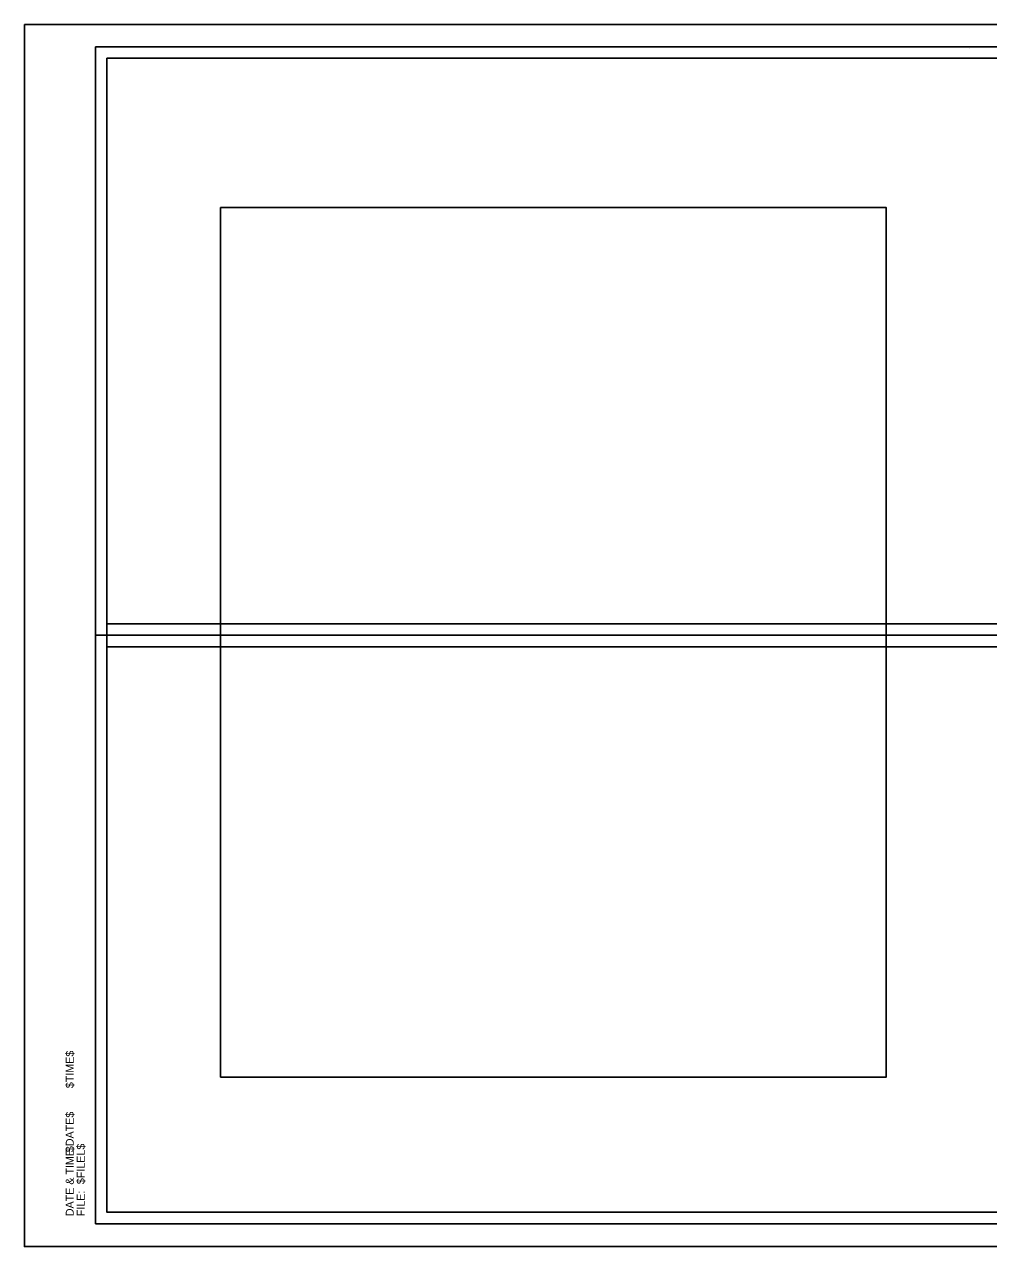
# Model space of a CAD drawing. Extents: x 1369290 to 1369980, y 379348 to 379562.
# Drawn here: x 1369646.8 to 1369815.1, y 379348.4 to 379561.7 of the extents above; entities that cross this region are included whole.
import ezdxf

# ---------------------------------------------------------------- set-up
doc = ezdxf.new("R2010")
doc.units = 0
for name, color, linetype in [('Default', 7, 'Continuous'), ('R_Border', 7, 'Continuous'), ('R_Border Notes', 7, 'Continuous'), ('R_Border Plan-Plan', 7, 'Continuous'), ('R_No Plot', 7, 'Continuous')]:
    doc.layers.add(name, color=color, linetype=linetype)

msp = doc.modelspace()

# ---------------------------------------------------------------- linework, layer by layer
at = {"layer": 'Default'}
msp.add_lwpolyline([(1369681.07, 379377.98), (1369797.24, 379377.98), (1369797.24, 379529.77), (1369681.07, 379529.77)], close=True, dxfattribs=at)
at = {"layer": 'R_Border'}
for p, q in [((1369659.23, 379557.83), (1369975.41, 379557.83)), ((1369659.23, 379352.37), (1369659.23, 379557.83)), ((1369811.75, 379557.57), (1369811.75, 379557.57)), ((1369811.75, 379557.57), (1369811.75, 379557.57)), ((1369659.23, 379352.37), (1369659.23, 379352.37)), ((1369975.41, 379352.37), (1369659.23, 379352.37))]:
    msp.add_line(p, q, dxfattribs=at)
at = {"layer": 'R_Border Plan-Plan'}
msp.add_line((1369659.23, 379455.1), (1369975.41, 379455.1), dxfattribs=at)
at = {"layer": 'R_No Plot'}
for points in [[(1369646.82, 379561.73), (1369980.16, 379561.73), (1369980.16, 379348.39), (1369646.82, 379348.39)], [(1369973.41, 379457.1), (1369661.23, 379457.1), (1369661.23, 379555.83), (1369910.77, 379555.83), (1369910.77, 379545.95), (1369928.31, 379545.95), (1369952.41, 379545.95), (1369952.41, 379523.62), (1369973.41, 379523.62)], [(1369661.23, 379555.83), (1369910.77, 379555.83), (1369910.77, 379545.95), (1369928.31, 379545.95), (1369952.41, 379545.95), (1369952.41, 379523.62), (1369973.41, 379523.62), (1369973.41, 379354.37), (1369661.23, 379354.37)], [(1369661.23, 379453.1), (1369973.41, 379453.1), (1369973.41, 379354.37), (1369661.23, 379354.37)]]:
    msp.add_lwpolyline(points, close=True, dxfattribs=at)

# ---------------------------------------------------------------- texts
at = {"layer": 'R_Border Notes'}
for s, height, p in [('$TIME$', 1.397, (1369655.43, 379376.04)), ('$DATE$', 1.397, (1369655.43, 379364.87)), ('DATE & TIME:', 1.3968, (1369655.43, 379353.69)), ('$FILEL$', 1.397, (1369657.35, 379359.28)), ('FILE: ', 1.397, (1369657.35, 379353.69))]:
    msp.add_text(s, height=height, rotation=90, dxfattribs=at).set_placement(p)

doc.saveas('drawing.dxf')
